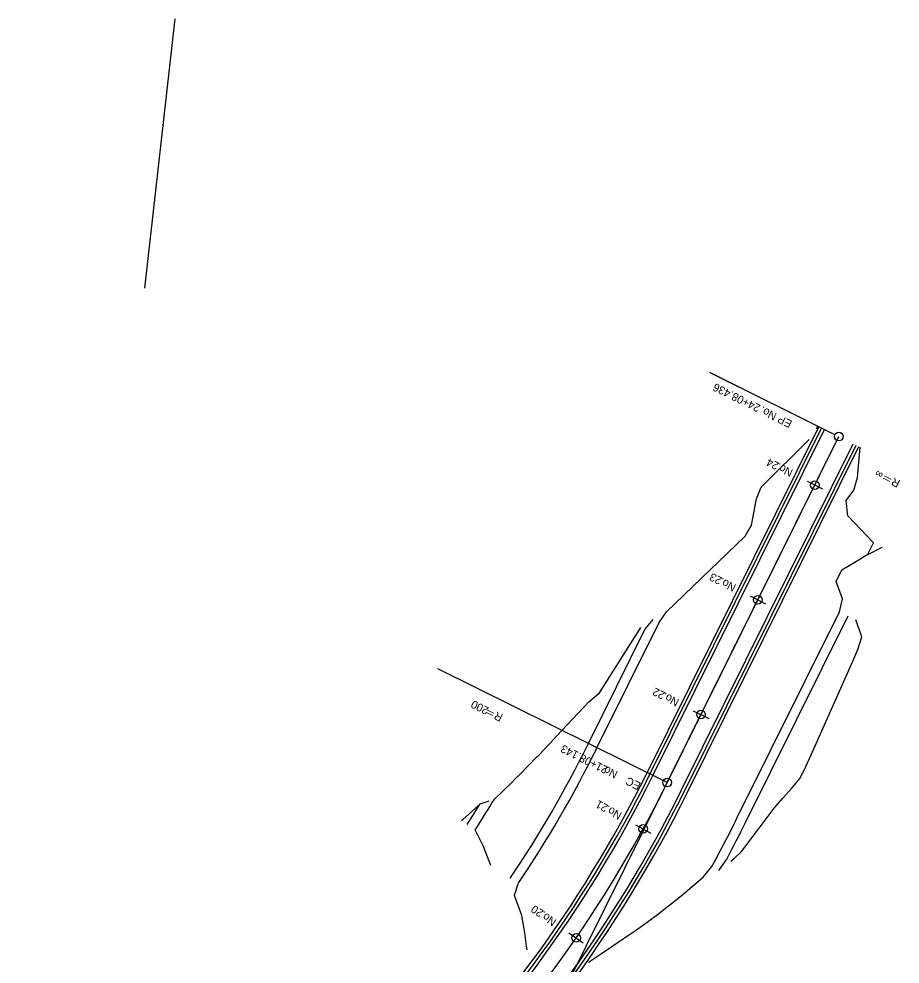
# Model space of a CAD drawing. Extents: x 46574 to 46965, y 10694 to 11089.
# Drawn here: x 46827.8 to 46965.4, y 10941.4 to 11088.9 of the extents above; entities that cross this region are included whole.
import ezdxf

# ---------------------------------------------------------------- set-up
doc = ezdxf.new("R2010")
doc.units = 0
for name, color, linetype in [('Default', 7, 'Continuous'), ('作業レイヤ1', 7, 'Continuous'), ('地形_土崖 コンクリート、堅固な石積等斜面（地理院地図Vector）', 7, 'Continuous'), ('建物_普通建物_普通建物（地理院地図Vector）', 7, 'Continuous'), ('建物_普通建物_普通建物（外周線）（地理院地図Vector）', 7, 'Continuous'), ('河川_通常部（地理院地図Vector）', 7, 'Continuous'), ('現況_地形_三角形_頂点', 7, 'Continuous'), ('現況_地形_単点標高', 7, 'Continuous'), ('等高線等深線_等高線_主曲線通常部（地理院地図Vector）', 7, 'Continuous'), ('道路_通常部_通常部（地理院地図Vector）', 7, 'Continuous')]:
    doc.layers.add(name, color=color, linetype=linetype)

msp = doc.modelspace()

# ---------------------------------------------------------------- linework, layer by layer
at = {"layer": 'Default'}
for p, q in [((46852.14, 11088.94), (46847.4, 11046.87)), ((46955.22, 11024.01), (46935.66, 11033.7)), ((46935.66, 11033.7), (46940.14, 11031.48)), ((46896.47, 10904.04), (46955.82, 11023.71)), ((46929.03, 10969.69), (46955.82, 11023.71)), ((46955.82, 11023.71), (46955.82, 11023.71)), ((46952.07, 11016.15), (46952.07, 11016.15)), ((46943.19, 10998.23), (46943.19, 10998.23)), ((46929.03, 10969.69), (46893.2, 10987.47)), ((46934.3, 10980.31), (46934.3, 10980.31)), ((46929.03, 10969.69), (46929.03, 10969.69)), ((46925.26, 10962.47), (46925.26, 10962.47)), ((46914.8, 10945.44), (46914.8, 10945.44))]:
    msp.add_line(p, q, dxfattribs=at)
for centre in [(46955.82, 11023.71), (46952.07, 11016.15), (46943.19, 10998.23), (46934.3, 10980.31), (46929.03, 10969.69), (46925.26, 10962.47), (46914.8, 10945.44)]:
    msp.add_circle(centre, 0.675, dxfattribs=at)
msp.add_arc((46749.86, 11058.56), 200, 293.3699, 333.6189, dxfattribs=at)
msp.add_arc((46749.86, 11058.56), 200, 293.3699, 333.6189, dxfattribs=at)
at = {"layer": '作業レイヤ1'}
msp.add_line((46929.03, 10969.69), (46955.82, 11023.71), dxfattribs=at)
msp.add_arc((46749.86, 11058.56), 200, 293.3699, 333.6189, dxfattribs=at)
at = {"layer": '地形_土崖 コンクリート、堅固な石積等斜面（地理院地図Vector）'}
for p, q in [((46926.28, 10970.9), (46953.13, 11025.04)), ((46931.65, 10968.23), (46958.51, 11022.37))]:
    msp.add_line(p, q, dxfattribs=at)
for radius in [197, 203]:
    msp.add_arc((46749.86, 11058.56), radius, 293.3699, 333.5778, dxfattribs=at)
at = {"layer": '建物_普通建物_普通建物（地理院地図Vector）'}
for p, q in [((46926.73, 10970.68), (46953.58, 11024.82)), ((46931.21, 10968.45), (46958.06, 11022.6))]:
    msp.add_line(p, q, dxfattribs=at)
for radius in [197.5, 202.5]:
    msp.add_arc((46749.86, 11058.56), radius, 293.3699, 333.5778, dxfattribs=at)
at = {"layer": '建物_普通建物_普通建物（外周線）（地理院地図Vector）'}
for p, q in [((46925.83, 10971.12), (46952.69, 11025.26)), ((46932.1, 10968.01), (46958.96, 11022.15))]:
    msp.add_line(p, q, dxfattribs=at)
for radius in [196.5, 203.5]:
    msp.add_arc((46749.86, 11058.56), radius, 293.3699, 333.5778, dxfattribs=at)
at = {"layer": '現況_地形_三角形_頂点'}
msp.add_line((46952.37, 11024.93), (46952.48, 11025.36), dxfattribs=at)
at = {"layer": '現況_地形_単点標高'}
for p, q in [((46960.37, 11005.33), (46962.6, 11006.46)), ((46941.26, 10963.45), (46957.26, 10995.71)), ((46937.1, 10955.99), (46938.32, 10957.76))]:
    msp.add_line(p, q, dxfattribs=at)
for points in [[(46918.01, 10975.01), (46927.79, 10994.71), (46928.91, 10996.38), (46941.19, 11008.15), (46942.16, 11009.9), (46942.95, 11013.98), (46943.71, 11015.83), (46951.19, 11023.28)], [(46939.92, 10964.12), (46955.92, 10996.38), (46956.39, 10998.38), (46955.43, 11001.09), (46956.28, 11002.9), (46958.33, 11004.12), (46960.36, 11005.34), (46961.25, 11007.13), (46957.24, 11011.35), (46956.95, 11013.73), (46958.14, 11015.37), (46958.74, 11017.31), (46959.13, 11022.06)], [(46916.67, 10975.67), (46925.55, 10993.58), (46926.85, 10995.17)], [(46938.97, 10957.41), (46939.42, 10957.81), (46940.64, 10958.96), (46941.96, 10960.7), (46943.27, 10962.46), (46943.37, 10962.58), (46945.72, 10965.72), (46947.09, 10967.27), (46948.47, 10968.82), (46949.78, 10970.4), (46950.67, 10972.2), (46951.51, 10974.01), (46958.02, 10988.64), (46958.77, 10990.5), (46959.39, 10992.43), (46958.5, 10995.1)], [(46901.7, 10966.56), (46902.05, 10967.09), (46903.38, 10968.37), (46904.7, 10969.67), (46905.29, 10970.26), (46906.01, 10970.98), (46907.32, 10972.3), (46908.63, 10973.64), (46908.97, 10973.99), (46909.93, 10974.99), (46911.22, 10976.36), (46912.5, 10977.75), (46912.59, 10977.85), (46916.78, 10982.3), (46918.46, 10983.71), (46924.91, 10993.9)], [(46896.91, 10963.72), (46897.14, 10963.92), (46898.47, 10965.15), (46899.8, 10966.39)], [(46897.8, 10963.14), (46897.96, 10963.39), (46898.9, 10964.88), (46899.83, 10966.37), (46901.24, 10966.84)], [(46901.5, 10956.77), (46900.35, 10959.72), (46899.06, 10962.33)], [(46916.72, 10941.65), (46918.59, 10942.89), (46920.38, 10944.1), (46922.22, 10945.35), (46923.75, 10946.4), (46924.06, 10946.62), (46925.9, 10947.91), (46927.71, 10949.23), (46928.83, 10950.12), (46929.45, 10950.62), (46931.19, 10952.03), (46932.92, 10953.46), (46933.71, 10954.12), (46934.66, 10954.91), (46935.99, 10956.6)], [(46907.16, 10943.59), (46907.08, 10944.16), (46906.8, 10946.25), (46906.31, 10948.95), (46905.18, 10952.04), (46905.16, 10952.1), (46905.76, 10953.91)]]:
    msp.add_lwpolyline(points, dxfattribs=at)
for radius, start, end in [(186.27, 326.1293, 333.5778), (187.77, 326.1293, 333.5778), (177.54, 327.179, 328.789), (212.23, 331.2859, 333.5778), (213.73, 331.8589, 333.5778)]:
    msp.add_arc((46749.86, 11058.56), radius, start, end, dxfattribs=at)
at = {"layer": '等高線等深線_等高線_主曲線通常部（地理院地図Vector）'}
msp.add_line((46929.03, 10969.69), (46955.82, 11023.71), dxfattribs=at)
msp.add_arc((46749.86, 11058.56), 200, 293.3699, 333.6189, dxfattribs=at)
at = {"layer": '道路_通常部_通常部（地理院地図Vector）'}
for p, q in [((46950.86, 11016.75), (46953.28, 11015.55)), ((46941.98, 10998.83), (46944.39, 10997.63)), ((46933.09, 10980.91), (46935.51, 10979.71)), ((46924.08, 10963.12), (46926.45, 10961.82)), ((46913.68, 10946.21), (46915.91, 10944.68))]:
    msp.add_line(p, q, dxfattribs=at)

# ---------------------------------------------------------------- texts
at = {"layer": 'Default'}
for s, p in [('24+08.436', (46943.69, 11028.58)), ('EP No.', (46948.65, 11026.12)), ('R＝∞', (46965.51, 11016.81)), ('200', (46901.29, 10981.36)), ('R＝', (46903.48, 10980.27)), ('21+08.143', (46919.92, 10972.12)), ('EC\u3000No.', (46925.02, 10969.59))]:
    msp.add_text(s, height=1.25, rotation=153.6189, dxfattribs=at).set_placement(p)
at = {"layer": '河川_通常部（地理院地図Vector）'}
for s, rotation, p in [('24', 153.6189, (46946.58, 11019.57)), ('No.', 153.6189, (46948.77, 11018.49)), ('23', 153.6189, (46937.7, 11001.65)), ('No.', 153.6189, (46939.88, 11000.57)), ('22', 153.6189, (46928.81, 10983.73)), ('No.', 153.6189, (46930.99, 10982.65)), ('21', 151.2859, (46919.92, 10966.11)), ('No.', 151.2859, (46922.06, 10964.94)), ('20', 145.5564, (46909.84, 10949.6)), ('No.', 145.5564, (46911.85, 10948.22))]:
    msp.add_text(s, height=1.25, rotation=rotation, dxfattribs=at).set_placement(p)

doc.saveas('drawing.dxf')
